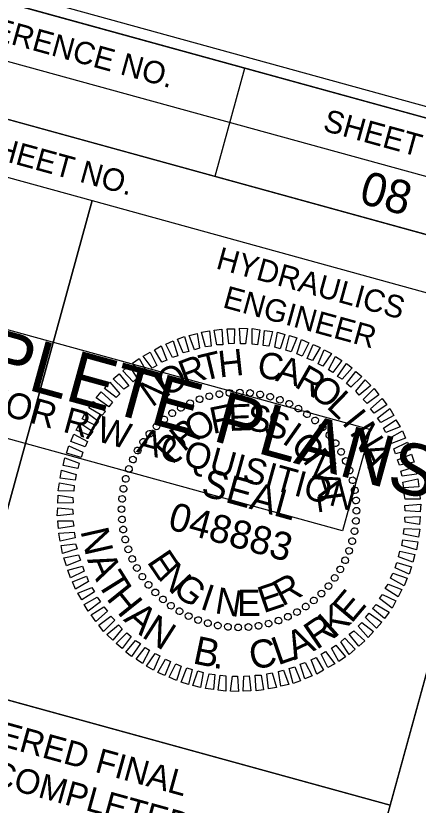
# Model space of a CAD drawing. Extents: x 1641063 to 2864602, y 841295 to 973236.
# Drawn here: x 1642960 to 1643049.9, y 842189.2 to 842365.5 of the extents above; entities that cross this region are included whole.
import ezdxf

# ---------------------------------------------------------------- set-up
doc = ezdxf.new("R2010")
doc.units = 0
for name, color, linetype in [('Default', 7, 'Continuous'), ('Old_Level_1', 7, 'Continuous'), ('Prop CMT Concrete Structures', 7, 'Continuous'), ('Prop CMT Shoulder Point', 7, 'Continuous'), ('Prop Dimension Text', 7, 'Continuous'), ('Prop DSN Text', 7, 'Continuous'), ('Prop Easement Construction', 7, 'Continuous')]:
    doc.layers.add(name, color=color, linetype=linetype)

msp = doc.modelspace()

# ---------------------------------------------------------------- linework, layer by layer
at = {"layer": 'Old_Level_1'}
msp.add_lwpolyline([(1642891.27, 842289.47), (1642897.51, 842312.13), (1643039.24, 842273.13), (1643033, 842250.47)], close=True, dxfattribs=at)
at = {"layer": 'Prop CMT Concrete Structures'}
for p, q in [((1642887.23, 842374.88), (1643080.1, 842321.79)), ((1642883.91, 842362.79), (1643076.79, 842309.74)), ((1642883.91, 842362.79), (1643076.79, 842309.74)), ((1643011.08, 842353.74), (1643004.49, 842329.62)), ((1642977.06, 842324.21), (1642947.23, 842215.77))]:
    msp.add_line(p, q, dxfattribs=at)
for points in [[(1643083.47, 842333.88), (1641637.2, 842731.89), (1641358.6, 841719.52), (1642804.85, 841321.52)], [(1641358.6, 841719.52), (1641637.16, 842731.87), (1642890.57, 842386.98), (1642850.76, 842242.29), (1643043.63, 842189.2), (1642804.85, 841321.52)], [(1642890.57, 842386.98), (1643083.47, 842333.88), (1643076.79, 842309.74), (1642883.91, 842362.79)], [(1642880.6, 842350.75), (1642977.06, 842324.21), (1642947.21, 842215.73), (1642850.76, 842242.29)], [(1642977.06, 842324.21), (1643073.47, 842297.69), (1643043.63, 842189.2), (1642947.21, 842215.73)]]:
    msp.add_lwpolyline(points, close=True, dxfattribs=at)
at = {"layer": 'Prop Dimension Text'}
msp.add_lwpolyline([(1641209.95, 841757.82), (1642816.23, 841315.8), (1643096.16, 842332.97), (1641489.87, 842775.01)], close=True, dxfattribs=at)
at = {"layer": 'Prop DSN Text'}
msp.add_line((1642850.76, 842242.29), (1643043.63, 842189.22), dxfattribs=at)
msp.add_line((1642850.76, 842242.29), (1643043.63, 842189.22), dxfattribs=at)
at = {"layer": 'Prop Easement Construction'}
for p, q in [((1643003.26, 842280.53), (1643003.26, 842280.53)), ((1643005.49, 842281.04), (1643005.49, 842281.04)), ((1643007.73, 842281.33), (1643007.73, 842281.33)), ((1643010.01, 842281.39), (1643010.01, 842281.39)), ((1643012.34, 842281.22), (1643012.34, 842281.22)), ((1643014.6, 842280.97), (1643014.6, 842280.97)), ((1643016.84, 842280.45), (1643016.84, 842280.45)), ((1642998.94, 842279.05), (1642998.94, 842279.05)), ((1643001.03, 842279.86), (1643001.03, 842279.86)), ((1643019.03, 842279.73), (1643019.03, 842279.73)), ((1643021.12, 842278.81), (1643021.12, 842278.81)), ((1642996.88, 842277.96), (1642996.88, 842277.96)), ((1643023.13, 842277.81), (1643023.13, 842277.81)), ((1642993.13, 842275.36), (1642993.13, 842275.36)), ((1642994.95, 842276.78), (1642994.95, 842276.78)), ((1643025.07, 842276.56), (1643025.07, 842276.56)), ((1643026.86, 842275.12), (1643026.86, 842275.12)), ((1642991.4, 842273.86), (1642991.4, 842273.86)), ((1643028.58, 842273.6), (1643028.58, 842273.6)), ((1642989.88, 842272.14), (1642989.88, 842272.14)), ((1643030.08, 842271.87), (1643030.08, 842271.87)), ((1642988.45, 842270.35), (1642988.45, 842270.35)), ((1643031.5, 842270.05), (1643031.5, 842270.05)), ((1642987.19, 842268.4), (1642987.19, 842268.4)), ((1643032.68, 842268.13), (1643032.68, 842268.13)), ((1642986.19, 842266.39), (1642986.19, 842266.39)), ((1643033.77, 842266.07), (1643033.77, 842266.07)), ((1642985.28, 842264.31), (1642985.28, 842264.31)), ((1643034.58, 842263.97), (1643034.58, 842263.97)), ((1642984.55, 842262.12), (1642984.55, 842262.12)), ((1643035.25, 842261.74), (1643035.25, 842261.74)), ((1642984.03, 842259.88), (1642984.03, 842259.88)), ((1643035.76, 842259.51), (1643035.76, 842259.51)), ((1642983.78, 842257.62), (1642983.78, 842257.62)), ((1643036.05, 842257.28), (1643036.05, 842257.28)), ((1642983.61, 842255.29), (1642983.61, 842255.29)), ((1643009.86, 842255.14), (1643009.86, 842255.14)), ((1643036.11, 842254.99), (1643036.11, 842254.99)), ((1642983.67, 842253), (1642983.67, 842253)), ((1643035.95, 842252.66), (1643035.95, 842252.66)), ((1642983.96, 842250.77), (1642983.96, 842250.77)), ((1643035.69, 842250.4), (1643035.69, 842250.4)), ((1642984.47, 842248.54), (1642984.47, 842248.54)), ((1643035.17, 842248.16), (1643035.17, 842248.16)), ((1642985.14, 842246.31), (1642985.14, 842246.31)), ((1643034.45, 842245.97), (1643034.45, 842245.97)), ((1642985.95, 842244.21), (1642985.95, 842244.21)), ((1643033.53, 842243.89), (1643033.53, 842243.89)), ((1642987.04, 842242.15), (1642987.04, 842242.15)), ((1643032.53, 842241.88), (1643032.53, 842241.88)), ((1642988.22, 842240.23), (1642988.22, 842240.23)), ((1643031.28, 842239.93), (1643031.28, 842239.93)), ((1642989.65, 842238.41), (1642989.65, 842238.41)), ((1643029.85, 842238.14), (1643029.85, 842238.14)), ((1642991.14, 842236.68), (1642991.14, 842236.68)), ((1643028.33, 842236.42), (1643028.33, 842236.42)), ((1642992.86, 842235.16), (1642992.86, 842235.16)), ((1643026.59, 842234.92), (1643026.59, 842234.92)), ((1642994.65, 842233.72), (1642994.65, 842233.72)), ((1643024.77, 842233.5), (1643024.77, 842233.5)), ((1642996.6, 842232.47), (1642996.6, 842232.47)), ((1642998.61, 842231.47), (1642998.61, 842231.47)), ((1643020.79, 842231.23), (1643020.79, 842231.23)), ((1643022.85, 842232.32), (1643022.85, 842232.32)), ((1643000.69, 842230.55), (1643000.69, 842230.55)), ((1643002.88, 842229.83), (1643002.88, 842229.83)), ((1643005.13, 842229.31), (1643005.13, 842229.31)), ((1643014.23, 842229.24), (1643014.23, 842229.24)), ((1643016.47, 842229.75), (1643016.47, 842229.75)), ((1643018.69, 842230.42), (1643018.69, 842230.42)), ((1643007.38, 842229.06), (1643007.38, 842229.06)), ((1643009.71, 842228.89), (1643009.71, 842228.89)), ((1643012, 842228.95), (1643012, 842228.95))]:
    msp.add_line(p, q, dxfattribs=at)
for points in [[(1642999.92, 842290.89), (1642998.75, 842294.1), (1643000.53, 842294.51), (1643001.04, 842291.25)], [(1643002.41, 842291.54), (1643001.52, 842294.8), (1643003.27, 842295.1), (1643003.64, 842291.71)], [(1643004.91, 842292.04), (1643004.35, 842295.31), (1643006.03, 842295.53), (1643006.26, 842292.02)], [(1643007.6, 842292.21), (1643007.22, 842295.55), (1643008.9, 842295.6), (1643008.76, 842292.29)], [(1643010.2, 842292.25), (1643009.96, 842295.71), (1643011.77, 842295.62), (1643011.33, 842292.23)], [(1643012.78, 842292.18), (1643012.8, 842295.63), (1643014.51, 842295.35), (1643014.03, 842292.02)], [(1643015.29, 842291.86), (1643015.56, 842295.24), (1643017.33, 842295), (1643016.54, 842291.7)], [(1643017.88, 842291.46), (1643018.47, 842294.82), (1643020.13, 842294.34), (1643019.09, 842291.1)], [(1642995.05, 842289.17), (1642993.5, 842292.16), (1642995.14, 842292.87), (1642996.19, 842289.58)], [(1642997.37, 842290.19), (1642996.16, 842293.26), (1642997.72, 842293.88), (1642998.64, 842290.52)], [(1643020.3, 842290.79), (1643021.15, 842294.08), (1643022.8, 842293.6), (1643021.5, 842290.43)], [(1643022.8, 842289.99), (1643023.84, 842293.23), (1643025.44, 842292.49), (1643023.96, 842289.47)], [(1642992.63, 842288.12), (1642990.97, 842290.92), (1642992.5, 842291.82), (1642993.77, 842288.58)], [(1643025.12, 842288.96), (1643026.41, 842292.08), (1643028.02, 842291.4), (1643026.3, 842288.49)], [(1643027.56, 842287.74), (1643028.91, 842290.9), (1643030.53, 842290.05), (1643028.56, 842287.21)], [(1642990.5, 842286.77), (1642988.45, 842289.51), (1642990.01, 842290.35), (1642991.52, 842287.38)], [(1643029.82, 842286.46), (1643031.39, 842289.4), (1643032.83, 842288.49), (1643030.8, 842285.83)], [(1642986.22, 842283.77), (1642983.93, 842286.19), (1642985.27, 842287.41), (1642987.13, 842284.56)], [(1642988.23, 842285.3), (1642986.11, 842287.95), (1642987.56, 842288.99), (1642989.18, 842286.03)], [(1643031.87, 842284.96), (1643033.85, 842287.85), (1643035.12, 842286.88), (1643032.94, 842284.31)], [(1643033.9, 842283.41), (1643035.94, 842286.08), (1643037.32, 842284.97), (1643034.87, 842282.57)], [(1642984.18, 842282.13), (1642981.73, 842284.38), (1642983.11, 842285.54), (1642985.23, 842282.84)], [(1643035.93, 842281.65), (1643038.04, 842284.19), (1643039.34, 842282.94), (1643036.74, 842280.8)], [(1642982.41, 842280.27), (1642979.84, 842282.27), (1642981.01, 842283.65), (1642983.26, 842281.07)], [(1643037.56, 842279.78), (1643040.08, 842282.26), (1643041.13, 842280.86), (1643038.52, 842278.88)], [(1642980.8, 842278.2), (1642977.95, 842280.17), (1642979.12, 842281.54), (1642981.59, 842279.18)], [(1642979.21, 842276.23), (1642976.31, 842277.94), (1642977.37, 842279.35), (1642980.04, 842277.15)], [(1643039.24, 842277.72), (1643041.83, 842280.03), (1643042.86, 842278.58), (1643040.03, 842276.77)], [(1642977.83, 842273.99), (1642974.86, 842275.45), (1642975.64, 842277.04), (1642978.51, 842274.95)], [(1643040.77, 842275.66), (1643043.52, 842277.76), (1643044.42, 842276.23), (1643041.53, 842274.65)], [(1643042.14, 842273.42), (1643044.92, 842275.24), (1643045.83, 842273.71), (1643042.69, 842272.42)], [(1642976.55, 842271.73), (1642973.51, 842272.94), (1642974.31, 842274.57), (1642977.22, 842272.69)], [(1642975.48, 842269.25), (1642972.31, 842270.39), (1642972.96, 842272.06), (1642976.04, 842270.4)], [(1643043.44, 842271.14), (1643046.35, 842272.82), (1643047.07, 842271.18), (1643043.89, 842269.95)], [(1643044.45, 842268.78), (1643047.48, 842270.27), (1643048.07, 842268.55), (1643044.81, 842267.66)], [(1642974.6, 842266.88), (1642971.34, 842267.83), (1642971.87, 842269.47), (1642975.01, 842268.07)], [(1642973.9, 842264.36), (1642970.57, 842265.06), (1642971.01, 842266.78), (1642974.21, 842265.58)], [(1643045.24, 842266.36), (1643048.42, 842267.6), (1643048.99, 842265.83), (1643045.69, 842265.17)], [(1643045.98, 842263.8), (1643049.27, 842264.84), (1643049.53, 842263.1), (1643046.34, 842262.68)], [(1642973.3, 842261.82), (1642969.91, 842262.26), (1642970.25, 842264.01), (1642973.51, 842263.06)], [(1642972.98, 842259.31), (1642969.51, 842259.44), (1642969.8, 842261.21), (1642973.09, 842260.58)], [(1643046.44, 842261.36), (1643049.81, 842262.11), (1643050.06, 842260.32), (1643046.66, 842260.11)], [(1643046.74, 842258.74), (1643050.17, 842259.27), (1643050.32, 842257.56), (1643046.97, 842257.55)], [(1642972.82, 842256.76), (1642969.38, 842256.62), (1642969.52, 842258.42), (1642972.78, 842257.9)], [(1643046.92, 842256.11), (1643050.47, 842256.44), (1643050.34, 842254.69), (1643047.01, 842254.95)], [(1642972.8, 842254.17), (1642969.26, 842253.84), (1642969.38, 842255.59), (1642972.72, 842255.33)], [(1642972.99, 842251.54), (1642969.56, 842251.01), (1642969.4, 842252.72), (1642972.75, 842252.73)], [(1643046.91, 842253.52), (1643050.35, 842253.66), (1643050.21, 842251.86), (1643046.94, 842252.38)], [(1643046.74, 842250.97), (1643050.22, 842250.84), (1643049.93, 842249.07), (1643046.63, 842249.7)], [(1642973.29, 842248.92), (1642969.91, 842248.17), (1642969.67, 842249.96), (1642973.07, 842250.17)], [(1642973.74, 842246.48), (1642970.45, 842245.44), (1642970.19, 842247.18), (1642973.38, 842247.6)], [(1643046.42, 842248.46), (1643049.82, 842248.02), (1643049.48, 842246.27), (1643046.21, 842247.22)], [(1642974.49, 842243.92), (1642971.31, 842242.68), (1642970.74, 842244.45), (1642974.04, 842245.11)], [(1643045.82, 842245.92), (1643049.15, 842245.22), (1643048.71, 842243.5), (1643045.51, 842244.7)], [(1643045.12, 842243.4), (1643048.39, 842242.45), (1643047.86, 842240.81), (1643044.71, 842242.21)], [(1642975.27, 842241.5), (1642972.24, 842240.01), (1642971.66, 842241.73), (1642974.91, 842242.62)], [(1642976.28, 842239.14), (1642973.37, 842237.46), (1642972.66, 842239.1), (1642975.83, 842240.33)], [(1643044.25, 842241.03), (1643047.41, 842239.89), (1643046.76, 842238.22), (1643043.68, 842239.88)], [(1643043.18, 842238.55), (1643046.21, 842237.34), (1643045.42, 842235.71), (1643042.5, 842237.59)], [(1642977.59, 842236.86), (1642974.8, 842235.04), (1642973.9, 842236.57), (1642977.04, 842237.86)], [(1643041.9, 842236.29), (1643044.87, 842234.83), (1643044.08, 842233.24), (1643041.22, 842235.33)], [(1642978.96, 842234.62), (1642976.21, 842232.52), (1642975.3, 842234.05), (1642978.19, 842235.63)], [(1642980.48, 842232.56), (1642977.89, 842230.25), (1642976.86, 842231.7), (1642979.7, 842233.51)], [(1643040.51, 842234.05), (1643043.42, 842232.34), (1643042.36, 842230.93), (1643039.68, 842233.13)], [(1642982.17, 842230.5), (1642979.64, 842228.02), (1642978.6, 842229.42), (1642981.21, 842231.4)], [(1643038.93, 842232.08), (1643041.77, 842230.11), (1643040.61, 842228.74), (1643038.14, 842231.1)], [(1642983.79, 842228.63), (1642981.68, 842226.09), (1642980.38, 842227.34), (1642982.98, 842229.48)], [(1643037.32, 842230.01), (1643039.88, 842228.01), (1643038.72, 842226.63), (1643036.46, 842229.21)], [(1642985.82, 842226.87), (1642983.79, 842224.2), (1642982.4, 842225.31), (1642984.85, 842227.71)], [(1643035.54, 842228.15), (1643037.99, 842225.9), (1643036.61, 842224.74), (1643034.5, 842227.44)], [(1642987.85, 842225.32), (1642985.87, 842222.43), (1642984.61, 842223.4), (1642986.78, 842225.97)], [(1643033.5, 842226.51), (1643035.8, 842224.09), (1643034.46, 842222.87), (1643032.6, 842225.72)], [(1642989.9, 842223.82), (1642988.33, 842220.88), (1642986.89, 842221.79), (1642988.93, 842224.45)], [(1643031.49, 842224.98), (1643033.62, 842222.33), (1643032.17, 842221.29), (1643030.55, 842224.25)], [(1642992.16, 842222.54), (1642990.81, 842219.38), (1642989.19, 842220.23), (1642991.16, 842223.07)], [(1643027.1, 842222.16), (1643028.76, 842219.36), (1643027.23, 842218.46), (1643025.95, 842221.7)], [(1643029.22, 842223.51), (1643031.27, 842220.77), (1643029.71, 842219.93), (1643028.21, 842222.9)], [(1642994.6, 842221.32), (1642993.31, 842218.2), (1642991.71, 842218.88), (1642993.43, 842221.79)], [(1642996.93, 842220.29), (1642995.88, 842217.05), (1642994.29, 842217.79), (1642995.77, 842220.81)], [(1643024.67, 842221.11), (1643026.22, 842218.12), (1643024.58, 842217.41), (1643023.54, 842220.7)], [(1642999.42, 842219.49), (1642998.58, 842216.2), (1642996.92, 842216.68), (1642998.22, 842219.85)], [(1643001.84, 842218.82), (1643001.25, 842215.46), (1642999.59, 842215.94), (1643000.64, 842219.18)], [(1643017.31, 842218.74), (1643018.21, 842215.48), (1643016.45, 842215.18), (1643016.08, 842218.57)], [(1643019.8, 842219.39), (1643020.97, 842216.18), (1643019.2, 842215.77), (1643018.68, 842219.03)], [(1643022.36, 842220.09), (1643023.57, 842217.02), (1643022, 842216.4), (1643021.08, 842219.76)], [(1643004.44, 842218.42), (1643004.16, 842215.04), (1643002.39, 842215.28), (1643003.18, 842218.58)], [(1643006.95, 842218.1), (1643006.93, 842214.65), (1643005.22, 842214.93), (1643005.69, 842218.26)], [(1643009.52, 842218.03), (1643009.77, 842214.57), (1643007.95, 842214.66), (1643008.39, 842218.05)], [(1643012.12, 842218.07), (1643012.51, 842214.73), (1643010.82, 842214.68), (1643010.97, 842217.99)], [(1643014.81, 842218.24), (1643015.37, 842214.97), (1643013.7, 842214.75), (1643013.47, 842218.26)]]:
    msp.add_lwpolyline(points, close=True, dxfattribs=at)
for centre, major_axis in [((1643010.04, 842281.37), (0.005, 0.753)), ((1643001.06, 842279.85), (-0.253, 0.709)), ((1643003.24, 842280.52), (-0.19, 0.729)), ((1643005.48, 842281), (-0.126, 0.742)), ((1643007.75, 842281.28), (-0.061, 0.751)), ((1643012.32, 842281.25), (0.071, 0.75)), ((1643014.59, 842280.94), (0.136, 0.741)), ((1643016.82, 842280.43), (0.2, 0.726)), ((1643019, 842279.73), (0.262, 0.706)), ((1642996.9, 842277.94), (-0.372, 0.655)), ((1642998.94, 842278.98), (-0.314, 0.685)), ((1643021.11, 842278.84), (0.323, 0.68)), ((1643023.13, 842277.76), (0.381, 0.65)), ((1642994.96, 842276.73), (-0.428, 0.62)), ((1643025.05, 842276.52), (0.436, 0.614)), ((1642993.14, 842275.34), (-0.48, 0.58)), ((1643026.86, 842275.12), (0.488, 0.574)), ((1642991.44, 842273.81), (-0.529, 0.536)), ((1643028.53, 842273.56), (0.536, 0.529)), ((1642989.88, 842272.13), (-0.574, 0.488)), ((1643030.07, 842271.86), (0.58, 0.48)), ((1642988.48, 842270.33), (-0.614, 0.436)), ((1643031.45, 842270.04), (0.62, 0.428)), ((1642987.24, 842268.41), (-0.65, 0.381)), ((1643032.66, 842268.1), (0.655, 0.372)), ((1642986.17, 842266.38), (-0.68, 0.323)), ((1643033.71, 842266.06), (0.685, 0.314)), ((1642985.28, 842264.28), (-0.706, 0.262)), ((1643034.57, 842263.94), (0.709, 0.253)), ((1642984.57, 842262.1), (-0.726, 0.2)), ((1643035.24, 842261.76), (0.729, 0.19)), ((1642984.06, 842259.87), (-0.741, 0.136)), ((1643035.72, 842259.52), (0.742, 0.126)), ((1642983.75, 842257.6), (-0.75, 0.071)), ((1643036, 842257.25), (0.751, 0.061)), ((1642983.63, 842255.32), (-0.753, 0.005)), ((1643036.09, 842254.96), (0.753, -0.005)), ((1642983.72, 842253.03), (-0.751, -0.061)), ((1643035.97, 842252.68), (0.75, -0.071)), ((1642984, 842250.76), (-0.742, -0.126)), ((1643035.66, 842250.41), (0.741, -0.136)), ((1642984.48, 842248.52), (-0.729, -0.19)), ((1643035.15, 842248.18), (0.726, -0.2)), ((1642985.16, 842246.34), (-0.709, -0.253)), ((1643034.45, 842246), (0.706, -0.262)), ((1642986.02, 842244.22), (-0.685, -0.314)), ((1643033.56, 842243.9), (0.68, -0.323)), ((1642987.06, 842242.18), (-0.655, -0.372)), ((1643032.49, 842241.87), (0.65, -0.381)), ((1642988.28, 842240.24), (-0.62, -0.428)), ((1643031.24, 842239.95), (0.614, -0.436)), ((1642989.66, 842238.42), (-0.58, -0.48)), ((1643029.84, 842238.15), (0.574, -0.488)), ((1642991.19, 842236.72), (-0.536, -0.529)), ((1643028.28, 842236.47), (0.529, -0.536)), ((1642992.87, 842235.16), (-0.488, -0.574)), ((1642994.67, 842233.76), (-0.436, -0.614)), ((1643026.59, 842234.94), (0.48, -0.58)), ((1642996.6, 842232.52), (-0.381, -0.65)), ((1643022.82, 842232.34), (0.372, -0.655)), ((1643024.76, 842233.55), (0.428, -0.62)), ((1642998.62, 842231.44), (-0.323, -0.68)), ((1643000.73, 842230.55), (-0.262, -0.706)), ((1643018.67, 842230.43), (0.253, -0.709)), ((1643020.79, 842231.3), (0.314, -0.685)), ((1643002.9, 842229.85), (-0.2, -0.726)), ((1643005.13, 842229.34), (-0.136, -0.741)), ((1643007.4, 842229.03), (-0.071, -0.75)), ((1643009.69, 842228.91), (-0.005, -0.753)), ((1643011.97, 842229), (0.061, -0.751)), ((1643014.24, 842229.28), (0.126, -0.742)), ((1643016.48, 842229.76), (0.19, -0.729))]:
    msp.add_ellipse(centre, major_axis=major_axis, ratio=0.999708, dxfattribs=at)

# ---------------------------------------------------------------- texts
at = {"layer": 'Default'}
for s, rotation, p in [('N', 282.6908, (1642974.43, 842250.48)), ('A', 293.3026, (1642975.89, 842244.03)), ('T', 302.0489, (1642977.96, 842238.99)), ('H', 308.7768, (1642980.07, 842235.36)), ('E', 49.8333, (1643034.96, 842229.61)), ('A', 318.6546, (1642983.89, 842230.54)), ('K', 41.6375, (1643031.07, 842226.29)), ('N', 327.4009, (1642987.93, 842226.87)), ('R', 34.2368, (1643027.19, 842223.8)), ('A', 25.4905, (1643022.23, 842221.54)), ('B', 348.1046, (1642999.32, 842220.93)), ('C', 9.8022, (1643012.69, 842219.45)), ('L', 19.2824, (1643018.53, 842220.4)), ('.', 355.7194, (1643003.94, 842219.83))]:
    msp.add_text(s, height=6.27, rotation=rotation, dxfattribs=at).set_placement(p)
at = {"layer": 'Old_Level_1'}
for s, height, p in [('INCOMPLETE PLANS', 11.52, (1642903.01, 842298.38)), ('DO NOT USE FOR R/W ACQUISITION', 5.76, (1642904.29, 842290.82))]:
    msp.add_text(s, height=height, rotation=344.6135, dxfattribs=at).set_placement(p)
at = {"layer": 'Prop CMT Concrete Structures'}
for s, height, p in [('PROJECT REFERENCE NO.', 5.0001, (1642909.66, 842372.68)), ('SHEET NO.', 5, (1643028.38, 842339.89)), ('R/W SHEET NO.', 5.0001, (1642936.43, 842338.81)), ('HYDRAULICS', 5, (1643004.5, 842309.11)), ('ENGINEER', 5, (1643006.02, 842300.43))]:
    msp.add_text(s, height=height, rotation=344.6135, dxfattribs=at).set_placement(p)
at = {"layer": 'Prop CMT Shoulder Point'}
msp.add_text('08', height=7.5, rotation=344.6135, dxfattribs=at).set_placement((1643036.4, 842323.76))
at = {"layer": 'Prop DSN Text'}
for s, p in [('DOCUMENT NOT CONSIDERED FINAL', (1642868.33, 842226.73)), ('DOCUMENT NOT CONSIDERED FINAL', (1642868.33, 842226.73)), ('UNLESS ALL SIGNATURES COMPLETED', (1642861.11, 842219.59)), ('UNLESS ALL SIGNATURES COMPLETED', (1642861.11, 842219.59))]:
    msp.add_text(s, height=5.5, rotation=344.6135, dxfattribs=at).set_placement(p)
at = {"layer": 'Prop Easement Construction'}
for s, height, rotation, p in [('H', 5.9, 6.233, (1643005.52, 842284.7)), ('R', 5.9, 20.634, (1642997.78, 842282.53)), ('T', 5.9, 13.4333, (1643001.79, 842283.88)), ('C', 5.9, 351.8334, (1643013.73, 842284.75)), ('A', 5.9, 344.6338, (1643017.81, 842284.03)), ('O', 5.9, 27.8352, (1642993.48, 842280.29)), ('R', 5.9, 330.2346, (1643022.02, 842282.74)), ('N', 5.9, 35.037, (1642990.4, 842277.95)), ('O', 5.9, 323.0347, (1643025.21, 842281.11)), ('L', 5.9, 315.8344, (1643029.19, 842278.09)), ('F', 5.9, 11.5805, (1643004.01, 842272.08)), ('E', 5.9, 2.2246, (1643007.64, 842272.77)), ('S', 5.9, 352.8691, (1643011.4, 842272.94)), ('O', 5.9, 30.2947, (1642999.9, 842269.95)), ('S', 5.9, 343.5139, (1643015.06, 842272.05)), ('I', 5.9, 308.6336, (1643032.67, 842274.61)), ('R', 5.9, 39.6532, (1642997.49, 842267.92)), ('I', 5.9, 324.8031, (1643019.24, 842270.23)), ('N', 5.9, 301.4324, (1643034.44, 842272.48)), ('P', 5.9, 49.0124, (1642995.03, 842265.1)), ('O', 5.9, 315.447, (1643021.08, 842269)), ('N', 5.9, 306.0901, (1643023.96, 842266.1)), ('A', 5.9, 294.2307, (1643036.67, 842268.72)), ('SEAL', 6.273, 344.6135, (1643001.16, 842258.45)), ('A', 5.9, 287.3738, (1643026.17, 842262.73)), ('L', 5.9, 278.0144, (1643027.25, 842258.72)), ('048883', 6.275, 344.6135, (1642993.72, 842250.95)), ('E', 5.9, 303.8904, (1642989.18, 842243.55)), ('N', 5.9, 313.2475, (1642991.52, 842240.03)), ('G', 5.9, 322.6037, (1642994.78, 842236.77)), ('R', 5.9, 28.0949, (1643019.53, 842233.5)), ('I', 5.9, 341.3147, (1643000.93, 842233.14)), ('E', 5.9, 18.7376, (1643015.33, 842232.04)), ('N', 5.9, 350.6699, (1643004.28, 842232.12)), ('E', 5.9, 0.0253, (1643009.45, 842231.44))]:
    msp.add_text(s, height=height, rotation=rotation, dxfattribs=at).set_placement(p)

doc.saveas('drawing.dxf')
